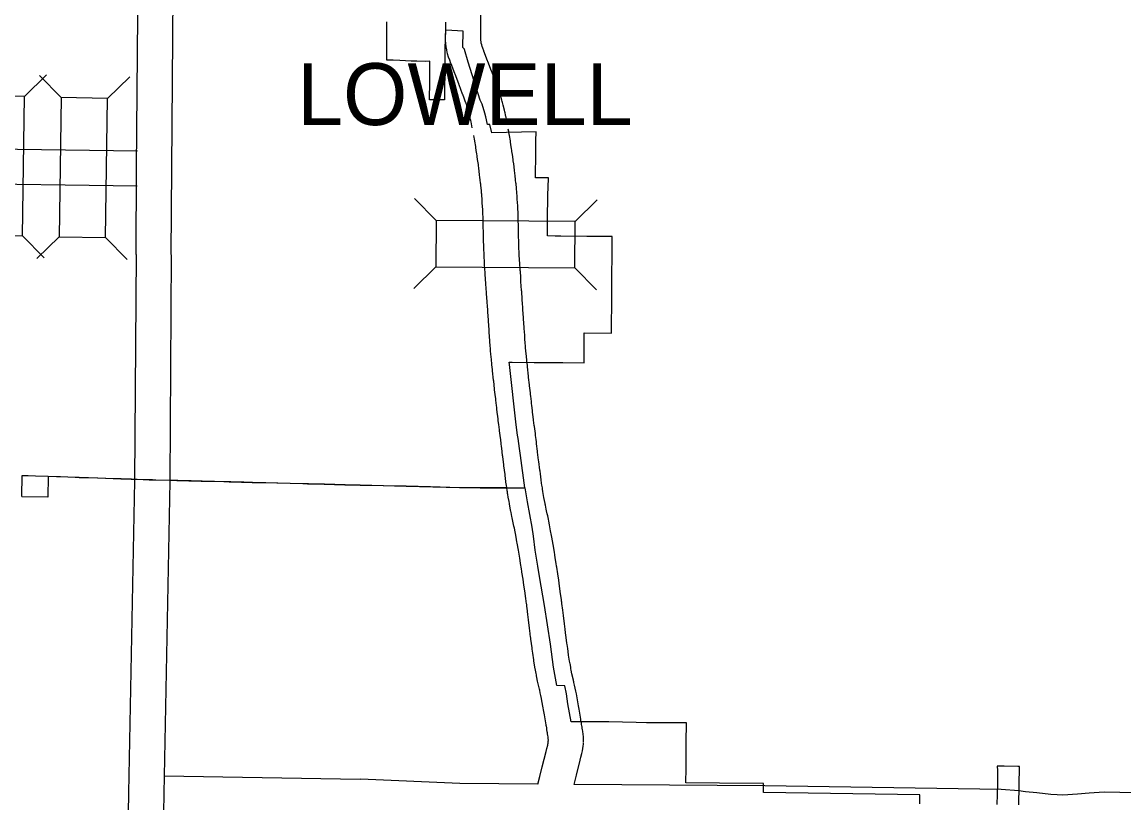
# Model space of a CAD drawing. Extents: x 670147 to 673275, y 705573 to 707613.
# Drawn here: x 670561.9 to 670703, y 707059.4 to 707159.4 of the extents above; entities that cross this region are included whole.
import ezdxf

# ---------------------------------------------------------------- set-up
doc = ezdxf.new("R2010")
doc.units = 0
for name, color, linetype in [('10', 7, 'Continuous'), ('15', 7, 'Continuous'), ('20', 7, 'Continuous'), ('6', 7, 'Continuous')]:
    doc.layers.add(name, color=color, linetype=linetype)

msp = doc.modelspace()

# ---------------------------------------------------------------- linework, layer by layer
at = {"layer": '10'}
for points in [[(670620.67, 707159.32), (670620.73, 707163.24), (670620.75, 707163.97), (670620.75, 707164.15), (670620.76, 707164.72), (670620.76, 707164.83), (670620.77, 707165.47), (670620.78, 707166.22), (670620.81, 707167.72), (670620.82, 707168.47), (670620.83, 707168.97)], [(670618.88, 707148.61), (670618.76, 707148.97), (670618.72, 707149.1), (670618.7, 707149.15), (670618.52, 707149.66), (670618.35, 707150.1), (670618.32, 707150.17), (670617.87, 707151.34), (670617.84, 707151.42), (670617.82, 707151.48), (670617.35, 707152.71), (670617.31, 707152.81), (670616.84, 707154.05), (670616.82, 707154.09), (670616.66, 707154.5), (670616.53, 707154.9), (670616.4, 707155.32), (670616.34, 707155.58), (670616.3, 707155.76), (670616.29, 707155.84), (670616.22, 707156.2), (670616.17, 707156.64), (670616.14, 707157.09), (670616.14, 707157.34), (670616.14, 707157.5), (670616.14, 707157.54), (670616.15, 707158.41), (670616.15, 707158.45)], [(670616.15, 707158.45), (670616.15, 707158.56), (670616.16, 707158.76), (670616.17, 707159.39)], [(670623.15, 707150.04), (670623.03, 707150.4), (670622.99, 707150.53), (670622.95, 707150.64), (670622.73, 707151.24), (670622.55, 707151.7), (670622.52, 707151.78), (670622.08, 707152.95), (670622.05, 707153.03), (670622.03, 707153.08), (670621.55, 707154.32), (670621.52, 707154.41), (670621.04, 707155.66), (670621.02, 707155.7), (670620.89, 707156.05), (670620.81, 707156.27), (670620.76, 707156.46), (670620.72, 707156.61), (670620.71, 707156.66), (670620.68, 707156.86), (670620.65, 707157.06), (670620.64, 707157.26), (670620.64, 707157.39), (670620.64, 707157.49), (670620.65, 707158.33), (670620.65, 707158.37)], [(670620.65, 707158.37), (670620.65, 707158.48), (670620.66, 707158.69), (670620.67, 707159.32)], [(670623.97, 707146.7), (670623.88, 707147.2), (670623.86, 707147.29), (670623.82, 707147.49), (670623.76, 707147.77), (670623.73, 707147.88), (670623.68, 707148.11), (670623.53, 707148.75), (670623.44, 707149.08), (670623.4, 707149.21), (670623.35, 707149.39), (670623.17, 707149.98)], [(670619.56, 707145.84), (670619.46, 707146.34), (670619.44, 707146.42), (670619.41, 707146.57), (670619.36, 707146.82), (670619.34, 707146.93), (670619.3, 707147.1), (670619.17, 707147.62), (670619.1, 707147.89), (670619.06, 707148.01), (670619.03, 707148.13), (670618.87, 707148.67)], [(670625.05, 707139.68), (670625.01, 707140.02), (670624.97, 707140.39), (670624.96, 707140.42), (670624.86, 707141.24), (670624.81, 707141.64), (670624.79, 707141.78), (670624.69, 707142.45), (670624.64, 707142.83), (670624.62, 707142.93), (670624.58, 707143.18), (670624.51, 707143.67), (670624.45, 707144.06), (670624.44, 707144.1), (670624.43, 707144.18), (670624.31, 707144.88), (670624.24, 707145.24), (670624.22, 707145.39), (670624.17, 707145.66)], [(670620.58, 707139.19), (670620.54, 707139.5), (670620.5, 707139.84), (670620.5, 707139.87), (670620.4, 707140.66), (670620.35, 707141.02), (670620.33, 707141.17), (670620.24, 707141.81), (670620.19, 707142.16), (670620.17, 707142.25), (670620.13, 707142.51), (670620.07, 707142.96), (670620.01, 707143.32), (670620, 707143.36), (670619.99, 707143.45), (670619.88, 707144.12), (670619.82, 707144.45), (670619.79, 707144.59), (670619.74, 707144.86)], [(670552.08, 707143.25), (670576.68, 707142.91)], [(670551.97, 707138.75), (670576.64, 707138.41)], [(670620.98, 707132.54), (670620.97, 707133.13), (670620.96, 707133.24), (670620.95, 707133.84), (670620.94, 707134.17), (670620.93, 707134.39), (670620.93, 707134.49), (670620.92, 707134.73), (670620.9, 707135.35), (670620.89, 707135.45), (670620.89, 707135.5), (670620.88, 707135.61), (670620.83, 707136.43), (670620.83, 707136.48), (670620.83, 707136.53), (670620.76, 707137.36), (670620.75, 707137.47), (670620.73, 707137.69), (670620.68, 707138.24), (670620.67, 707138.33), (670620.63, 707138.65), (670620.62, 707138.75), (670620.58, 707139.19)], [(670625.48, 707132.64), (670625.46, 707133.22), (670625.46, 707133.34), (670625.45, 707133.96), (670625.44, 707134.3), (670625.43, 707134.52), (670625.43, 707134.63), (670625.42, 707134.9), (670625.39, 707135.56), (670625.39, 707135.65), (670625.38, 707135.71), (670625.38, 707135.85), (670625.32, 707136.71), (670625.32, 707136.79), (670625.31, 707136.88), (670625.24, 707137.74), (670625.23, 707137.89), (670625.21, 707138.11), (670625.16, 707138.68), (670625.14, 707138.8), (670625.11, 707139.14), (670625.1, 707139.23), (670625.05, 707139.68)], [(670622.06, 707115.61), (670622.01, 707116.12), (670621.97, 707116.55), (670621.97, 707116.55), (670621.94, 707116.84), (670621.9, 707117.34), (670621.87, 707117.64), (670621.86, 707117.89), (670621.81, 707118.54), (670621.79, 707118.72), (670621.78, 707118.97), (670621.72, 707119.85), (670621.71, 707119.98), (670621.63, 707121.07), (670621.62, 707121.25), (670621.55, 707122.24), (670621.54, 707122.42), (670621.49, 707123.15), (670621.47, 707123.4), (670621.46, 707123.6), (670621.39, 707124.58), (670621.38, 707124.72), (670621.37, 707124.77), (670621.34, 707125.28), (670621.3, 707125.88), (670621.29, 707125.97), (670621.26, 707126.42), (670621.22, 707127.13), (670621.21, 707127.27), (670621.14, 707128.32), (670621.13, 707128.53), (670621.12, 707128.59), (670621.07, 707129.45), (670621.06, 707129.62), (670621.06, 707129.7), (670621.03, 707130.32), (670621.02, 707130.86), (670621.02, 707130.92), (670621.01, 707131.19), (670620.99, 707131.88), (670620.99, 707131.99), (670620.99, 707132.04), (670620.98, 707132.54)], [(670626.54, 707116.08), (670626.49, 707116.56), (670626.45, 707116.95), (670626.45, 707116.95), (670626.42, 707117.25), (670626.38, 707117.71), (670626.36, 707117.98), (670626.34, 707118.23), (670626.29, 707118.87), (670626.28, 707119.03), (670626.27, 707119.28), (670626.2, 707120.16), (670626.2, 707120.29), (670626.12, 707121.38), (670626.11, 707121.56), (670626.04, 707122.55), (670626.03, 707122.73), (670625.98, 707123.46), (670625.96, 707123.71), (670625.95, 707123.91), (670625.88, 707124.89), (670625.87, 707125.02), (670625.86, 707125.07), (670625.83, 707125.58), (670625.79, 707126.17), (670625.79, 707126.26), (670625.76, 707126.72), (670625.71, 707127.43), (670625.7, 707127.56), (670625.63, 707128.62), (670625.62, 707128.83), (670625.61, 707128.87), (670625.57, 707129.68), (670625.56, 707129.81), (670625.56, 707129.89), (670625.53, 707130.49), (670625.52, 707130.99), (670625.51, 707131.05), (670625.51, 707131.3), (670625.49, 707131.98), (670625.49, 707132.09), (670625.49, 707132.14), (670625.48, 707132.64)], [(670628.48, 707100.03), (670628.48, 707100.03), (670628.38, 707100.73), (670628.37, 707100.78), (670628.27, 707101.53), (670628.23, 707101.87), (670628.21, 707102.01), (670628.07, 707103.14), (670628.05, 707103.27), (670627.92, 707104.32), (670627.91, 707104.43), (670627.91, 707104.44), (670627.79, 707105.38), (670627.76, 707105.62), (670627.72, 707105.94), (670627.65, 707106.47), (670627.63, 707106.69), (670627.51, 707107.59), (670627.49, 707107.75), (670627.41, 707108.42), (670627.35, 707108.87), (670627.32, 707109.11), (670627.28, 707109.47), (670627.25, 707109.67), (670627.18, 707110.3), (670627.15, 707110.54), (670627.12, 707110.8), (670627.04, 707111.49), (670627.02, 707111.69), (670626.99, 707111.92), (670626.9, 707112.79), (670626.88, 707112.93), (670626.77, 707113.89), (670626.76, 707114.04), (670626.62, 707115.24), (670626.62, 707115.27), (670626.61, 707115.4), (670626.55, 707115.97), (670626.54, 707116.08)], [(670624.03, 707099.39), (670623.92, 707100.08), (670623.91, 707100.16), (670623.91, 707100.18), (670623.81, 707100.95), (670623.76, 707101.31), (670623.75, 707101.45), (670623.6, 707102.58), (670623.59, 707102.71), (670623.46, 707103.76), (670623.44, 707103.87), (670623.44, 707103.88), (670623.32, 707104.82), (670623.29, 707105.06), (670623.25, 707105.38), (670623.19, 707105.92), (670623.16, 707106.13), (670623.05, 707107.03), (670623.03, 707107.19), (670622.94, 707107.86), (670622.89, 707108.31), (670622.86, 707108.55), (670622.81, 707108.93), (670622.79, 707109.13), (670622.71, 707109.77), (670622.68, 707110.02), (670622.65, 707110.29), (670622.57, 707110.98), (670622.55, 707111.19), (670622.52, 707111.42), (670622.42, 707112.29), (670622.41, 707112.43), (670622.3, 707113.4), (670622.29, 707113.54), (670622.15, 707114.75), (670622.15, 707114.77), (670622.13, 707114.92), (670622.07, 707115.5), (670622.06, 707115.61)], [(670624.67, 707095.89), (670624.63, 707096.08), (670624.52, 707096.61), (670624.49, 707096.74), (670624.47, 707096.83), (670624.46, 707096.9), (670624.3, 707097.72), (670624.3, 707097.76), (670624.26, 707097.98), (670624.16, 707098.54), (670624.11, 707098.88), (670624.08, 707099.03), (670624.05, 707099.22), (670624.03, 707099.36)], [(670629.07, 707096.82), (670629.03, 707097), (670628.93, 707097.51), (670628.9, 707097.64), (670628.88, 707097.73), (670628.88, 707097.76), (670628.73, 707098.52), (670628.73, 707098.53), (670628.69, 707098.76), (670628.6, 707099.29), (670628.55, 707099.59), (670628.53, 707099.75), (670628.5, 707099.93), (670628.47, 707100.07)], [(670630.5, 707088.72), (670630.37, 707089.61), (670630.35, 707089.72), (670630.3, 707090.08), (670630.18, 707090.77), (670630.12, 707091.17), (670630.07, 707091.49), (670629.9, 707092.5), (670629.74, 707093.42), (670629.7, 707093.63), (670629.59, 707094.25), (670629.49, 707094.76), (670629.44, 707095), (670629.35, 707095.47), (670629.3, 707095.73), (670629.21, 707096.17), (670629.15, 707096.42), (670629.07, 707096.82)], [(670626.06, 707088.05), (670625.92, 707088.94), (670625.91, 707089.03), (670625.85, 707089.36), (670625.74, 707090.05), (670625.68, 707090.46), (670625.63, 707090.76), (670625.46, 707091.75), (670625.31, 707092.65), (670625.27, 707092.83), (670625.16, 707093.42), (670625.07, 707093.91), (670625.03, 707094.13), (670624.94, 707094.58), (670624.89, 707094.82), (670624.8, 707095.25), (670624.75, 707095.49), (670624.67, 707095.89)], [(670626.5, 707084.88), (670626.41, 707085.56), (670626.27, 707086.54), (670626.17, 707087.29), (670626.06, 707088.05)], [(670630.96, 707085.47), (670630.87, 707086.16), (670630.73, 707087.17), (670630.62, 707087.94), (670630.5, 707088.72)], [(670631.45, 707081.62), (670631.44, 707081.64), (670631.36, 707082.32), (670631.23, 707083.4), (670631.14, 707084.1), (670631.04, 707084.92), (670631.01, 707085.13), (670631, 707085.18), (670630.98, 707085.37), (670630.96, 707085.47)], [(670626.98, 707081.06), (670626.98, 707081.08), (670626.89, 707081.77), (670626.76, 707082.85), (670626.67, 707083.54), (670626.57, 707084.35), (670626.55, 707084.55), (670626.54, 707084.59), (670626.52, 707084.79), (670626.5, 707084.88)], [(670627.64, 707076.41), (670627.58, 707076.77), (670627.44, 707077.6), (670627.43, 707077.67), (670627.43, 707077.72), (670627.31, 707078.56), (670627.24, 707079.1), (670627.21, 707079.28), (670627.07, 707080.35), (670627.04, 707080.56), (670627.03, 707080.64), (670626.98, 707081.06)], [(670632.07, 707077.22), (670632.01, 707077.54), (670631.89, 707078.32), (670631.88, 707078.35), (670631.88, 707078.36), (670631.77, 707079.17), (670631.7, 707079.69), (670631.67, 707079.87), (670631.53, 707080.92), (670631.51, 707081.13), (670631.5, 707081.21), (670631.45, 707081.62)], [(670632.54, 707074.99), (670632.53, 707075), (670632.5, 707075.13), (670632.32, 707075.93), (670632.23, 707076.38), (670632.19, 707076.57), (670632.18, 707076.61), (670632.16, 707076.77), (670632.07, 707077.25)], [(670628.16, 707073.96), (670628.15, 707073.96), (670628.12, 707074.12), (670627.92, 707074.99), (670627.82, 707075.48), (670627.78, 707075.67), (670627.76, 707075.79), (670627.73, 707075.97), (670627.65, 707076.39)], [(670629.01, 707069.4), (670629.01, 707069.41), (670628.8, 707070.68), (670628.73, 707071.1), (670628.61, 707071.79), (670628.52, 707072.27), (670628.48, 707072.47), (670628.41, 707072.79), (670628.34, 707073.15), (670628.26, 707073.49), (670628.19, 707073.83), (670628.16, 707073.96), (670628.16, 707073.96)], [(670633.45, 707070.12), (670633.45, 707070.13), (670633.24, 707071.4), (670633.17, 707071.85), (670633.04, 707072.6), (670632.94, 707073.11), (670632.9, 707073.35), (670632.82, 707073.71), (670632.74, 707074.1), (670632.65, 707074.48), (670632.57, 707074.84), (670632.54, 707074.99), (670632.53, 707075)], [(670633.79, 707067.2), (670633.8, 707067.51), (670633.79, 707067.84), (670633.75, 707068.24), (670633.71, 707068.52), (670633.71, 707068.58), (670633.68, 707068.77), (670633.64, 707068.98), (670633.63, 707069.06), (670633.62, 707069.1), (670633.61, 707069.16), (670633.6, 707069.21), (670633.56, 707069.49), (670633.55, 707069.52), (670633.52, 707069.7), (670633.51, 707069.76), (670633.47, 707069.98), (670633.47, 707070), (670633.45, 707070.12), (670633.45, 707070.13)], [(670629.29, 707067.27), (670629.3, 707067.47), (670629.29, 707067.58), (670629.28, 707067.74), (670629.26, 707067.86), (670629.23, 707068.04), (670629.2, 707068.25), (670629.19, 707068.33), (670629.18, 707068.37), (670629.15, 707068.52), (670629.15, 707068.56), (670629.12, 707068.74), (670629.12, 707068.76), (670629.09, 707068.94), (670629.08, 707069), (670629.04, 707069.21), (670629.03, 707069.26), (670629.01, 707069.4), (670629.01, 707069.41)], [(670629.01, 707065.98), (670629.1, 707066.36), (670629.22, 707066.8), (670629.25, 707066.94), (670629.27, 707067.06), (670629.28, 707067.18), (670629.29, 707067.25), (670629.3, 707067.37)], [(670633.37, 707064.89), (670633.47, 707065.26), (670633.59, 707065.75), (670633.66, 707066.05), (670633.72, 707066.37), (670633.76, 707066.68), (670633.78, 707066.92), (670633.79, 707067.11)], [(670627.96, 707061.79), (670628.21, 707062.79), (670628.52, 707064.04), (670629.01, 707065.98)], [(670632.59, 707061.76), (670632.89, 707062.94), (670633.37, 707064.89)], [(670580.11, 707062.89), (670605.19, 707062.46)], [(670627.96, 707061.79), (670617.95, 707061.87), (670605.26, 707062.46)], [(670710.38, 707060.7), (670709.51, 707060.59), (670707.88, 707060.47), (670706.87, 707060.49), (670706.05, 707060.54), (670704.46, 707060.7), (670700.47, 707060.78), (670698.55, 707060.64), (670697.03, 707060.51), (670695.16, 707060.4), (670694.43, 707060.42), (670693.62, 707060.49), (670691.83, 707060.7), (670690.37, 707060.84), (670689.55, 707060.96), (670687.26, 707061.11), (670657.02, 707061.57), (670632.59, 707061.76)]]:
    msp.add_lwpolyline(points, dxfattribs=at)
at = {"layer": '15'}
for points in [[(670576.52, 707129.63), (670576.57, 707140.7), (670576.9, 707179.83)], [(670581.02, 707129.61), (670581.07, 707140.67), (670581.4, 707179.71)], [(670576.52, 707129.64), (670576.32, 707100.63), (670575.55, 707060.68), (670574.89, 707021.12)], [(670581.02, 707129.6), (670580.82, 707100.57), (670580.05, 707060.6), (670579.39, 707021)]]:
    msp.add_lwpolyline(points, dxfattribs=at)
at = {"layer": '20'}
for p, q in [((670562.2, 707149.85), (670565.04, 707152.61)), ((670566.91, 707149.71), (670564.15, 707152.55)), ((670572.85, 707149.62), (670575.69, 707152.38)), ((670614.92, 707133.98), (670612.14, 707136.8)), ((670632.74, 707133.86), (670635.56, 707136.64)), ((670561.96, 707132.03), (670564.72, 707129.19)), ((670566.66, 707131.89), (670563.82, 707129.13)), ((670572.6, 707131.81), (670575.36, 707128.97)), ((670614.88, 707128.04), (670612.06, 707125.26)), ((670632.7, 707127.92), (670635.48, 707125.1))]:
    msp.add_line(p, q, dxfattribs=at)
for points in [[(670556.27, 707149.93), (670556.02, 707132.11), (670561.96, 707132.03), (670562.2, 707149.85)], [(670566.91, 707149.71), (670566.66, 707131.89), (670572.6, 707131.81), (670572.85, 707149.62)], [(670614.88, 707128.04), (670632.7, 707127.92), (670632.74, 707133.86), (670614.92, 707133.98)]]:
    msp.add_lwpolyline(points, close=True, dxfattribs=at)
at = {"layer": '6'}
for points in [[(670634.23, 707131.95), (670630.89, 707131.98), (670630.15, 707131.98), (670629.18, 707132), (670629.18, 707134.13), (670629.2, 707135.15), (670629.23, 707136.18), (670629.25, 707137.21), (670629.28, 707138.28), (670629.3, 707139.35), (670629.3, 707139.45), (670627.65, 707139.45), (670627.69, 707142.69), (670627.7, 707144.19), (670627.72, 707145.32), (670622.04, 707145.2), (670621.82, 707146.27), (670621.5, 707146.27), (670621.31, 707147.25), (670621.16, 707147.74), (670620.84, 707148.88), (670620.67, 707149.2), (670620.56, 707149.37), (670619.03, 707154.27), (670618.56, 707155.88), (670618.54, 707155.93), (670618.52, 707155.98), (670618.48, 707156.02), (670618.44, 707156.06), (670618.4, 707156.09), (670618.35, 707156.11), (670618.38, 707158.24), (670616.95, 707158.32), (670616.11, 707158.33), (670616.04, 707156), (670616.02, 707154.29), (670615.99, 707149.42), (670614.07, 707149.45), (670614.1, 707151.77), (670614.14, 707154.36), (670613.55, 707154.34), (670612.45, 707154.37), (670611.75, 707154.4), (670611.01, 707154.43), (670610.26, 707154.46), (670609.43, 707154.49), (670608.6, 707154.51), (670608.61, 707155.95), (670608.63, 707159.41)], [(670626.29, 707099.74), (670625.71, 707103.9), (670625.59, 707104.8), (670625.42, 707106.07), (670625.36, 707106.49), (670625.18, 707107.82), (670624.3, 707115.55), (670624.26, 707115.83), (670624.45, 707115.83), (670624.65, 707115.83), (670627.48, 707115.81), (670631.14, 707115.78), (670633.86, 707115.76), (670633.87, 707119.59), (670637.36, 707119.56), (670637.43, 707124.43), (670637.43, 707124.53), (670637.44, 707126.95), (670637.44, 707127.04), (670637.45, 707129.41), (670637.46, 707129.51), (670637.48, 707131.92), (670634.23, 707131.95)], [(670561.86, 707098.63), (670561.91, 707101.34), (670562.67, 707101.32), (670563.62, 707101.28), (670565.23, 707101.23)], [(670629.59, 707079.71), (670628.8, 707084.7), (670628.18, 707088.38), (670627.95, 707089.71), (670627.6, 707091.78), (670627.38, 707093.58), (670627.24, 707094.71), (670626.64, 707097.97), (670626.32, 707099.74), (670626.21, 707099.72), (670623.86, 707099.73), (670622.5, 707099.74), (670620.59, 707099.74), (670618.34, 707099.75), (670617.93, 707099.76), (670614.2, 707099.86), (670611.11, 707099.94), (670609.62, 707099.97), (670608.19, 707100.01), (670605.21, 707100.08), (670603.26, 707100.13), (670600.63, 707100.2), (670598.6, 707100.25), (670598.51, 707100.25), (670597.89, 707100.27), (670596.25, 707100.31), (670594.64, 707100.35), (670594.56, 707100.35), (670593.12, 707100.39), (670591.41, 707100.43), (670591.21, 707100.44), (670590.3, 707100.46), (670590.05, 707100.47), (670588.63, 707100.5), (670588.45, 707100.51), (670588.11, 707100.52), (670587.77, 707100.53), (670586.55, 707100.56), (670586.41, 707100.56), (670584.98, 707100.6), (670584.86, 707100.6), (670583.55, 707100.63), (670583.42, 707100.64), (670583.3, 707100.64), (670581.85, 707100.68), (670581.77, 707100.68), (670580.96, 707100.7), (670580.87, 707100.69), (670579.04, 707100.75), (670578.6, 707100.76), (670578.21, 707100.77), (670576.66, 707100.82), (670575.92, 707100.85), (670575.63, 707100.86), (670574.61, 707100.89), (670572.64, 707100.96), (670571.59, 707101), (670569.23, 707101.08), (670568.73, 707101.09), (670566.83, 707101.16), (670566.36, 707101.17), (670565.26, 707101.21), (670565.21, 707098.57), (670561.89, 707098.61)], [(670565.23, 707101.23), (670566.33, 707101.19), (670566.8, 707101.18), (670568.7, 707101.11), (670569.2, 707101.09), (670571.56, 707101.02)], [(670571.56, 707101.02), (670572.61, 707100.98), (670574.57, 707100.91), (670574.6, 707100.91), (670575.6, 707100.88), (670575.89, 707100.87), (670576.62, 707100.84), (670578.18, 707100.79), (670578.57, 707100.78), (670579.01, 707100.77), (670580.84, 707100.71), (670580.93, 707100.72), (670581.74, 707100.7), (670581.82, 707100.7), (670583.27, 707100.66), (670583.39, 707100.66), (670583.52, 707100.65), (670584.83, 707100.62), (670584.95, 707100.62), (670586.38, 707100.58), (670586.52, 707100.58), (670587.73, 707100.55), (670588.08, 707100.54), (670588.42, 707100.53), (670588.6, 707100.52), (670590.02, 707100.49), (670590.27, 707100.48), (670591.18, 707100.46), (670591.37, 707100.45), (670593.09, 707100.41), (670594.53, 707100.37), (670594.61, 707100.37), (670596.22, 707100.33), (670597.85, 707100.29), (670597.87, 707100.29), (670598.47, 707100.27), (670598.49, 707100.27), (670598.57, 707100.27), (670600.59, 707100.22), (670603.23, 707100.15), (670605.18, 707100.1), (670608.16, 707100.03), (670609.59, 707099.99), (670611.08, 707099.95), (670617.9, 707099.78), (670618.31, 707099.77), (670620.56, 707099.76), (670622.47, 707099.76), (670623.83, 707099.75), (670626.29, 707099.74)], [(670676.86, 707059.3), (670676.87, 707060.44), (670656.83, 707060.75), (670656.83, 707061.89), (670651.21, 707061.92), (670646.91, 707061.98), (670646.91, 707062.39), (670646.92, 707063.41), (670646.93, 707064.61), (670646.94, 707065.88), (670646.95, 707067.12), (670646.97, 707069.64), (670646.86, 707069.65), (670646.34, 707069.65), (670644.34, 707069.66), (670641.86, 707069.67), (670640.53, 707069.68), (670637.03, 707069.77), (670632.21, 707069.8), (670631.81, 707072.09), (670631.6, 707073.36), (670631.42, 707074.4), (670630.37, 707074.44), (670629.97, 707076.8), (670629.59, 707079.71)], [(670689.54, 707059.17), (670689.61, 707064.05), (670689.42, 707064.07), (670687.66, 707064.09), (670686.76, 707064.1), (670686.82, 707063.56), (670686.81, 707062.73), (670686.8, 707061.78), (670686.7, 707059.2)]]:
    msp.add_lwpolyline(points, dxfattribs=at)

# ---------------------------------------------------------------- texts
msp.add_text('LOWELL', height=7.92, dxfattribs=at).set_placement((670597.12, 707146.2))

doc.saveas('drawing.dxf')
